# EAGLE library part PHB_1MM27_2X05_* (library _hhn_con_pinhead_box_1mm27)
Pin Header Box-Type, 1.27mm/0.5"/50mil Pitch, 2x05 Circuits Note: see library description for an important note about THT-version
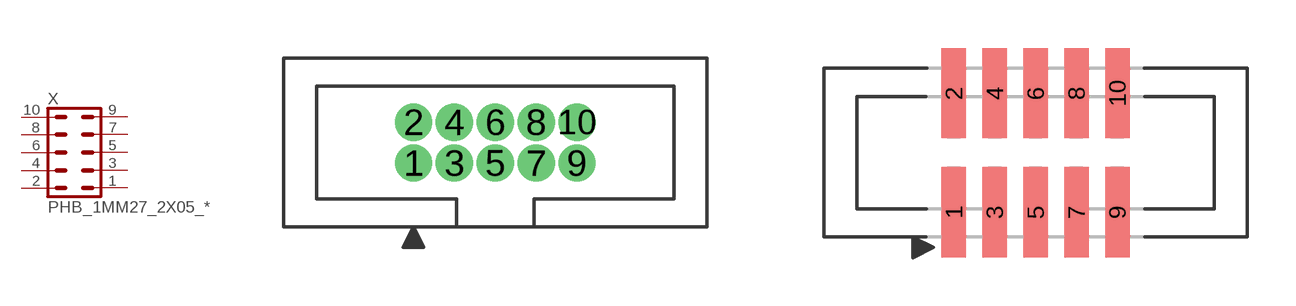
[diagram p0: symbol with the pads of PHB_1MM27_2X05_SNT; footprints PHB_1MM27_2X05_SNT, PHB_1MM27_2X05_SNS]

Designator prefix X

## PHB_1MM27_2X05_SNT  [PHB_1MM27_2X05_SNT]
1  1  pas
2  2  pas
3  3  pas
4  4  pas
5  5  pas
6  6  pas
7  7  pas
8  8  pas
9  9  pas
10  10  pas

## PHB_1MM27_2X05_SNS  [PHB_1MM27_2X05_SNS]
Pads as for PHB_1MM27_2X05_SNT

## Footprint PHB_1MM27_2X05_SNT (pad centres in mm)
Pin Header Box-Type, 1.27mm Pitch, 2x05 circuits, Straight, No Locking, THT Important Note: Diameter in this lbr is set to a specific value (NOT 'auto' = 0), this is ignored by actual eagle versions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
drill 0.65 pad 1 round: 1 -2.54,-0.635; 2 -2.54,0.635; 3 -1.27,-0.635; 4 -1.27,0.635; 5 0,-0.635; 6 0,0.635; 7 1.27,-0.635; 8 1.27,0.635; 9 2.54,-0.635; 10 2.54,0.635

## Footprint PHB_1MM27_2X05_SNS (pad centres in mm)
Pin Header Box-Type, 1.27mm Pitch, 2x05 circuits, Straight, No Locking, SMT
smd 0.76 x 2.8: 1 -2.54,-1.85; 2 -2.54,1.85; 3 -1.27,-1.85; 4 -1.27,1.85; 5 0,-1.85; 6 0,1.85; 7 1.27,-1.85; 8 1.27,1.85; 9 2.54,-1.85; 10 2.54,1.85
